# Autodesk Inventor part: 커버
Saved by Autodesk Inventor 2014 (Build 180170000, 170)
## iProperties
Created: 2025-06
Part Number: 커버
Material: 일반
Document SubType Name: Modeling
Designer: dg
Density: 1 g/cm^3
Appearance: 기본값
Author: dg
Author: jhkim
Creation Date: 2025-05-27
Sending System: Autodesk Inventor 2026
Preprocessor: ST-DEVELOPER v20.1
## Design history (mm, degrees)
node "커버1"
node "솔리드1"
node "기준1"
